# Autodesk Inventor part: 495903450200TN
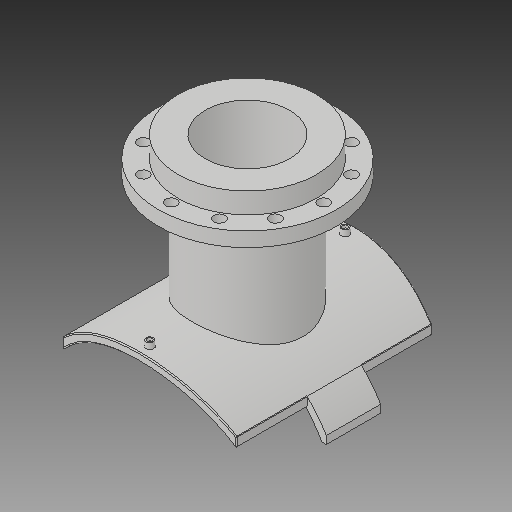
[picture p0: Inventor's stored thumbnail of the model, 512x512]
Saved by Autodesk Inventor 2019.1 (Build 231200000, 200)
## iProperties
Created: 2017-10
Part Number: 495903450200TN
Material: Generic
Description: PLASSON FLANGED BRANCH SADDLE 400-450X200
Document SubType Name: Modeling
Designer: KIM
Mass: 2339.99 g
Surface Area: 3251.55 cm^2
Volume: 2339.99 cm^3
Density: 1 g/cm^3
Appearance: Default
Author: KIM
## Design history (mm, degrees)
derived "495904_495903.ipt"
feature "Solid1::495904_495903.ipt"
feature "Solid2::495904_495903.ipt"
tag "TaggingFeature1"
body "Solid1"
other parameters: "d1" = 15, "d2" = 335.7, "d4" = 0, "d6" = 105, "d7" = 0, "d12" = 250.6, "d13" = 14, "d14" = 189, "d16" = 5 deg, "d18" = 4, "d19" = 14, "d20" = 0, "d21" = 3, "d22" = 0, "d23" = 515, "d36" = 189, "d38" = 0, "d39" = 2, "d41" = 163, "d42" = 268, "d43" = 344, "d46" = 214.4, "d47" = 16, "d48" = 10.4, "d49" = 192.5, "d51" = 459, "d53" = 0, "d54" = 22, "d55" = 147.5, "d57" = 0, "d59" = 360 deg, "d61" = 28, "d63" = 0, "d66" = 275, "d67" = 15, "d68" = 137.5, "d70" = 0, "d71" = 2, "d72" = 373, "d_1" = 268, "B_" = 373, "H_" = 275, "x_" = 15, "D_" = 16, "DN_" = 163, "D_1" = 344, "t_" = 28, "s_" = 22, "Dp_" = 295
